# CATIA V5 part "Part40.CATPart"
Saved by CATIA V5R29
Part number: spur gear_iso_ISO - Spur gear 0.5M 15T 20PA 12FW ---S15A75H50L5.0N
Revision: ANY
Definition: UNKNOWN
Nomenclature: spur gear_iso_ISO - Spur gear 0.5M 15T 20PA 12FW ---S15A75H50L5.0N
Source: Unknown
Bounding box of the stored display mesh (mm): x 0 to 12, y -4.249 to 4.179, z -4.237 to 4.237
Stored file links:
  C:\Users\Administrator\Desktop\프로젝트\Gripper\Part40.CATPart
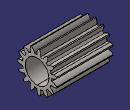
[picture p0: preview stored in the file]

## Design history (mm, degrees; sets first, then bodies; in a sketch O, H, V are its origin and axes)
Body1 "Bore" (main body)
  Solid1: solid without history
